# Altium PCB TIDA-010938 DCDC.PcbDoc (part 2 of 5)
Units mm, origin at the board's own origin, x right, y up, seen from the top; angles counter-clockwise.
Board outline 275 x 165 mm, 4 copper layers (Top Layer, Layer 1, Layer 2, Bottom Layer), stack 1.787 mm thick; 436 components, 216 nets, 1367 pads, 1992 vias.
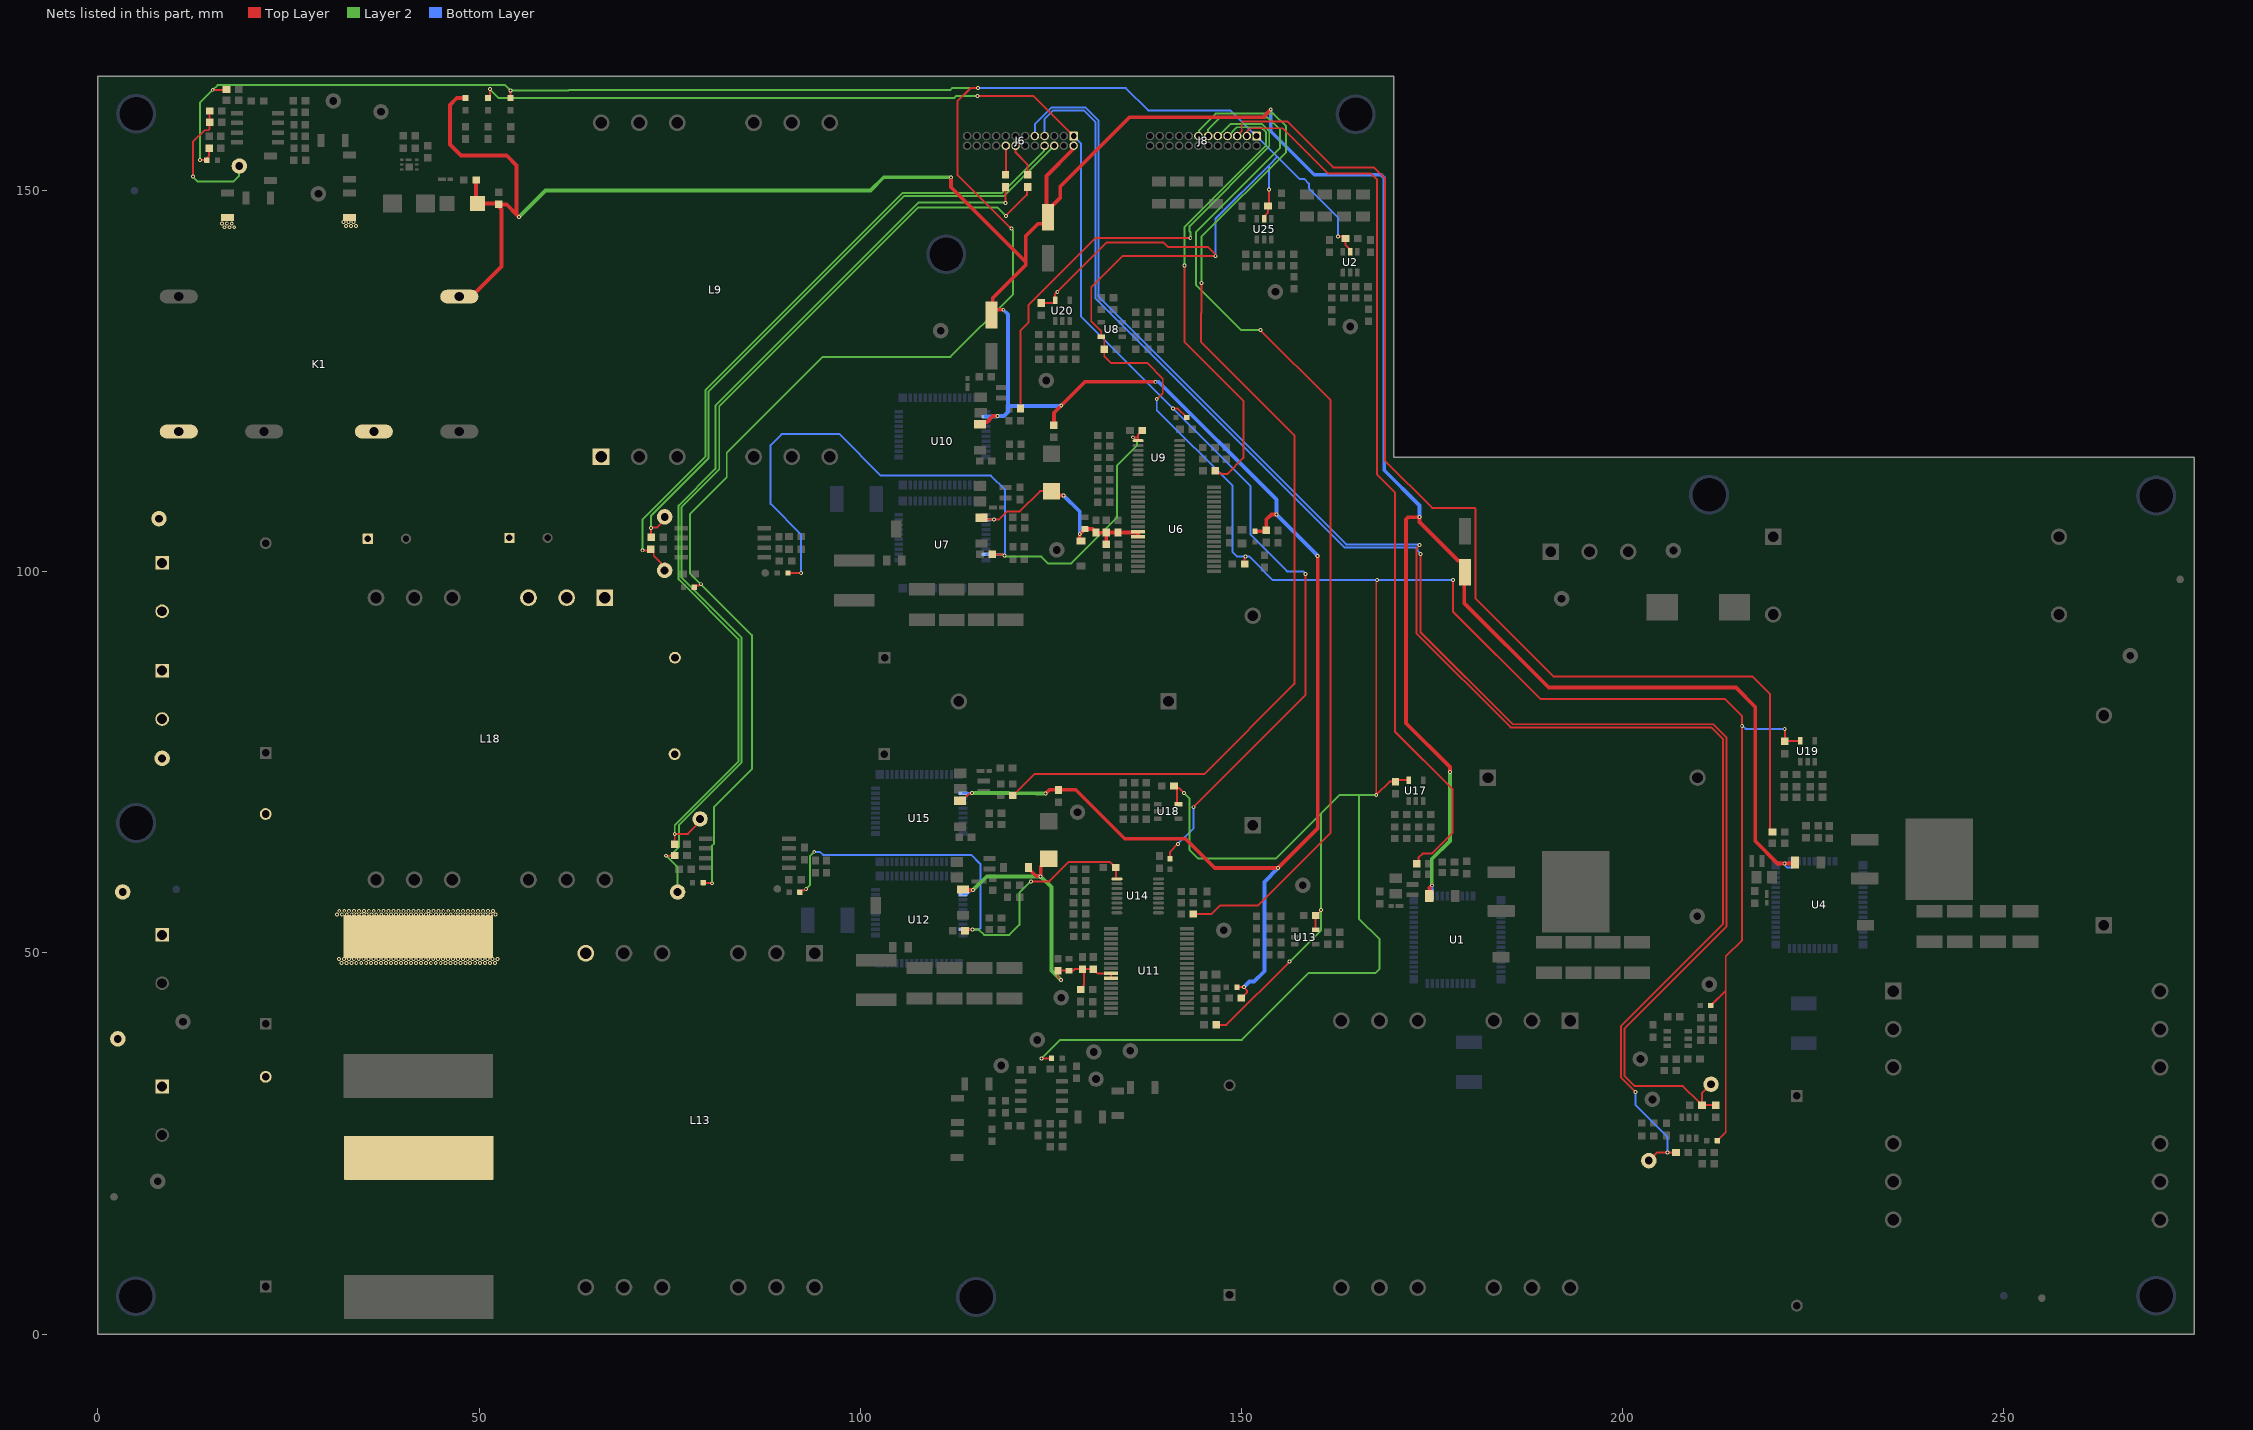
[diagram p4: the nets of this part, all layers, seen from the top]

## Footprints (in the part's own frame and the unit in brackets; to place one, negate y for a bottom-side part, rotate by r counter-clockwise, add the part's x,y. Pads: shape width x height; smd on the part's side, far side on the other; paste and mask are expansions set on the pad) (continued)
FP-B180986_PTH12-MFG [mm]
  rrect5% 2.2x2.2 hole 1.5 paste-1000 mask+0: 1(-18.5,15)
  round 2.2 hole 1.5 paste-1000 mask+0: 2(-18.5,10) 3(-18.5,5) 4(-18.5,-5) 5(-18.5,-10) 6(-18.5,-15) 7(18.5,-15) 8(18.5,-10) 9(18.5,-5) 10(18.5,5) 11(18.5,10) 12(18.5,15)
  silkscreen extent -22.12,-20.25 21.4,20.25, body extent -21.5,-20.35 21.5,20.35, height 0.25
FP-C4AKOBU4270A3YJ_RADIAL-MFG [mm]
  rrect5% 2.15x2.15 hole 1.4 paste-1000 mask+0: 1(-13.75,0)
  round 2.15 hole 1.4 paste-1000 mask+0: 2(13.75,0)
  silkscreen extent -16.35,-7.35 16.35,7.35, body extent -16.45,-7.45 16.45,7.45, height 0.25
FP-C4AKOBW5140A3JJ_RADIAL-MFG [mm]
  rrect5% 2.15x2.15 hole 1.4 paste-1000 mask+0: 1(-18.75,5.1)
  round 2.15 hole 1.4 paste-1000 mask+0: 2(18.75,5.1) 3(-18.75,-5.1) 4(18.75,-5.1)
  silkscreen extent -22.12,-14.5 21.5,14.5, body extent -21.6,-14.6 21.6,14.6, height 0.25
FP-C4AUJBU4240M1WJ_RADIAL-MFG [mm]
  rrect6% 1.55x1.55 hole 1 paste-1000 mask+0: 1(-13.75,0)
  round 1.55 hole 1 paste-1000 mask+0: 2(13.75,0)
  silkscreen extent -16.35,-5.85 16.35,5.85, body extent -16.45,-5.95 16.45,5.95, height 0.25
FP-C4AUJBU4600M18J_RADIAL-MFG [mm]
  rrect6% 1.55x1.55 hole 1 paste-1000 mask+0: 1(-13.75,0)
  round 1.55 hole 1 paste-1000 mask+0: 2(13.75,0)
  silkscreen extent -16.35,-8.35 16.35,8.35, body extent -16.45,-8.45 16.45,8.45, height 0.25
FP-C6D20065G_TO263-2-MFG [mm]
  rrect6% 1.54x3.56 smd paste+0 mask+0: 1(-2.54,-7.993) 2(2.54,-7.993)
  rrect1% 10.69x8.89 smd paste+0 mask+0: 3(0,1.773)
  silkscreen extent -5.14,-4.7 5.14,-3.05, body extent -5.45,-9.87 5.45,6.32, height 0.25
FP-CSD17318Q2_WSON6-MFG [mm]
  rrect33% 0.45x0.3 smd paste+0 mask+0: 1(-0.975,0.65) 2(-0.975,0) 3(-0.975,-0.65) 4(0.975,-0.65) 5(0.975,0) 6(0.975,0.65)
  rrect33% 0.75x0.3 smd paste-1000 mask+0: 7(0.095,-0.65)
  rrect11% 1x0.95 smd paste-1000 mask+0: 8(0,0.325)
  body extent -1.3,-1.15 1.3,1.15, height 0.25
FP-CSR0805FKR250_0805-MFG [mm]
  rrect10% 1x1.35 smd paste+0 mask+0: 1(-1,0) 2(1,0)
  silkscreen extent -0.3,-0.7 0.3,0.7, body extent -1.6,-0.8 1.6,0.8, height 0.25
FP-CSS2H-2512K-3L00F_2512-MFG [mm]
  rrect6% 1.8x3.4 smd paste+0 mask+0: 1(-2.6,0) 2(2.6,0)
  silkscreen extent -1.33,-1.63 1.33,1.63, body extent -3.17,-1.53 3.17,1.53, height 0.81
"FP-G7L-2A-X DC12_PTH_RELAY_52MM5_35MM5-MFG" [mm]
  rrect100% 5x1.8 hole 1.2 slot 4.4 at 0 deg paste-1000 mask+0: 0(18.4,9.1) 1(-18.4,9.1) 2(18.4,-8.6) 4(7.2,-8.6) 6(-7.2,-8.6) 8(-18.4,-8.6)
  silkscreen extent -26.97,-17.75 26.25,17.75, body extent -26.35,-17.85 26.35,17.85, height 0.25
FP-GB02SLT12-214_DO-214AA-MFG [mm]
  rrect5% 2.16x2.26 smd paste+0 mask+0: 1(-2.45,0) 2(2.45,0)
  silkscreen extent -4.3,-1.97 2.28,1.97, body extent -3.63,-2.07 3.63,2.07, height 0.25
"FP-KG DELLS1.22-JGKH-24_0603-MFG" [mm]
  rrect20% 1.05x0.5 smd paste-1000 mask+0: 1(-0.47,0)
  rrect20% 0.7x0.5 smd paste-1000 mask+0: 2(0.645,0)
  silkscreen extent -1.67,-0.63 0.75,0.63, body extent -1.09,-0.55 1.09,0.55, height 0.25
FP-MH1608-601Y_0603-MFG [mm]
  rrect14% 0.7x0.7 smd paste+0 mask+0: 1(-0.7,0) 2(0.7,0)
  silkscreen extent -0.87,-0.8 0.87,0.8, body extent -1.15,-0.6 1.15,0.6, height 0.25
FP-PTCEL13R102SBE_RADIAL-MFG [mm]
  rrect7% 1.35x1.35 hole 0.85 paste-1000 mask+0: 1(-2.5,0)
  round 1.35 hole 0.85 paste-1000 mask+0: 2(2.5,0)
  silkscreen extent -6.75,-3.5 6.75,3.5, body extent -6.85,-3.6 6.85,3.6, height 0.25
FP-R533R456050P0M_RADIAL-MFG [mm]
  rrect6% 1.55x1.55 hole 1 paste-1000 mask+0: 1(-13.75,0)
  round 1.55 hole 1 paste-1000 mask+0: 2(13.75,0)
  silkscreen extent -16.25,-8.15 16.25,8.15, body extent -16.35,-8.25 16.35,8.25, height 0.25
FP-SDEM20161T-4R7MS_SMD2-MFG [mm]
  rrect15% 0.65x1.6 smd paste+0 mask+0: 1(-0.675,0) 2(0.675,0)
  silkscreen extent -1.05,-1.22 1.05,1.2, body extent -1.15,-0.95 1.15,0.95, height 0.25
FP-SHF-112-01-L-D-TH_HDR24-MFG [mm]
  rrect9% 1.12x1.12 hole 0.74 paste-1000 mask+0: 1(-6.985,-0.89)
  round 1.12 hole 0.74 paste-1000 mask+0: 2(-6.985,0.38) 3(-5.715,-0.89) 4(-5.715,0.38) 5(-4.445,-0.89) 6(-4.445,0.38) 7(-3.175,-0.89) 8(-3.175,0.38) 9(-1.905,-0.89) 10(-1.905,0.38) 11(-0.635,-0.89) 12(-0.635,0.38) 13(0.635,-0.89) 14(0.635,0.38) 15(1.905,-0.89) 16(1.905,0.38) 17(3.175,-0.89) 18(3.175,0.38) 19(4.445,-0.89) 20(4.445,0.38) 21(5.715,-0.89) 22(5.715,0.38) 23(6.985,-0.89) 24(6.985,0.38)
  silkscreen extent -10.86,-3.46 10.86,2.86, body extent -10.96,-2.96 10.96,2.96, height 0.25
FP-SMBJ5350B-TP_SMB-MFG [mm]
  rrect4% 2.5x2.3 smd paste+0 mask+0: 1(-2.15,0) 2(2.15,0)
  silkscreen extent -4.12,-1.97 2.42,1.97, body extent -3.5,-2.07 3.5,2.07, height 0.25
FP-ZRB18AR61E106ME01L_0603-MFG [mm]
  rrect13% 0.75x0.9 smd paste+0 mask+0: 1(-0.775,0) 2(0.775,0)
  silkscreen extent 0,-0.5 0,0.5, body extent -1.25,-0.6 1.25,0.6, height 0.25
Harwin_S2751-46R [mm] "Test Point, SMT"
  rect 2.2x1.4 smd: 1(0,0)
  body extent -1,-0.6 1,0.6, height 1.4
IEC_HighVoltage_Small [mm]
  silkscreen extent -2.72,-2.24 2.72,2.47
IEC_HotSurface_Small [mm]
  silkscreen extent -2.72,-2.36 2.72,2.35
Keystone5001 [mil] "For Keystone 500x miniature loop terminals"
  round 80 hole 40: 1(0,0)
  silkscreen extent -52,-52 52,52, body extent -49,-49 49,49, height 182
Label_650x200 [mil] "Thermal Transfer Label"
  round 1 on Mech13: 0(0,0)
  silkscreen extent -325,-100 325,100, body extent -325,-100 325,100, height 1
Phoenix_1714955 [mm] "Terminal Block, 2x1, 6.35mm, TH"
  rect 1.8x1.8 hole 1.3: 1(-3.175,0)
  round 1.8 hole 1.3: 2(3.175,0)
  silkscreen extent -6.7,-7.9 6.35,4.6, body extent -6.92,-7.9 6.35,4.6, height 21.5
RQS0052C-C01-MFG [mm]
  rrect9% 1.15x1.1 smd paste+0 mask+0: 1(-5.725,5.2) 16(-5.725,-5.2) 27(5.725,-5.2) 42(5.725,5.2)
  rrect22% 1.15x0.45 smd paste+0 mask+0: 2(-5.725,4.225) 3(-5.725,3.575) 4(-5.725,2.925) 5(-5.725,2.275) 6(-5.725,1.625) 7(-5.725,0.975) 8(-5.725,0.325) 9(-5.725,-0.325) 10(-5.725,-0.975) 11(-5.725,-1.625) 12(-5.725,-2.275) 13(-5.725,-2.925) 14(-5.725,-3.575) 15(-5.725,-4.225) 28(5.725,-4.225) 29(5.725,-3.575) 30(5.725,-2.925) 31(5.725,-2.275) 32(5.725,-1.625) 33(5.725,-0.975) 34(5.725,-0.325) 35(5.725,0.325) 36(5.725,0.975) 37(5.725,1.625) 38(5.725,2.275) 39(5.725,2.925) 40(5.725,3.575) 41(5.725,4.225)
  rrect15% 0.665x1.15 smd paste+0 mask+0: 17(-2.043,-5.725) 52(-2.043,5.725)
  rrect22% 0.45x1.15 smd paste+0 mask+0: 18(-1.285,-5.725) 19(-0.635,-5.725) 20(0.015,-5.725) 21(0.665,-5.725) 22(1.315,-5.725) 23(1.965,-5.725) 24(2.615,-5.725) 25(3.265,-5.725) 26(3.915,-5.725) 43(3.915,5.725) 44(3.265,5.725) 45(2.615,5.725) 46(1.965,5.725) 47(1.315,5.725) 48(0.665,5.725) 49(0.015,5.725) 50(-0.635,5.725) 51(-1.285,5.725)
  silkscreen extent -7.02,-6.05 4.77,6.05, body extent -6,-6 6,6, height 1
SMA [mm] "Molded Diode, 2-Leads, Body 4.3x2.6mm, IPC Medium Density, based on OnSemi component dimensions and land pattern"
  rect 2x2 smd: 1(-2,0) 2(2,0)
  silkscreen extent -3.66,-1.57 2.79,1.58, body extent -2.6,-1.3 2.6,1.3, height 2.42
SOD-123 [mm] "On Semi recommended land pattern"
  rect 0.915x1.22 smd: 1(-1.637,0) 2(1.637,0)
  silkscreen extent -2.74,-1.17 2.03,1.17, body extent -1.93,-0.9 1.93,0.9, height 1.35
SRP1038A [mm] "SMD, 2-Leads, Body 11x10mm"
  rect 4.1x3.5 smd: 1(-4.75,0) 2(4.75,0)
  silkscreen extent -5,-5 5,5, body extent -5.2,-5 5.2,5, height 3.75
SRP2313AA [mm] "Shielded, metal alloy powder core"
  rrect2% 5.75x19.6 smd: 1(-9.125,0) 2(9.125,0)
  body extent -11.75,-11 11.75,11, height 12.61
TNPV1206 [mm] "VISHAY"
  rrect11% 0.9x1.7 smd: 1(-1.6,0) 2(1.6,0)
  silkscreen extent -2.4,-1.2 2.4,1.2, body extent -1.67,-0.87 1.67,0.87, height 0.65
TP_SM_1MM [mm] "1mm Test Point, SMT"
  round 1 smd paste-0.5: 1(0,0)
UWT_630x770 [mm] "SMD, 2-Leads, Dia 6.3mm"
  rrect6% 3.5x1.6 smd: 1(-2.7,0) 2(2.7,0)
  body extent -3.5,-3.3 3.5,3.3, height 8
WEEE_Minimum [mm] "WEEElie bin"
  silkscreen extent -2.42,-4.38 2.52,2.65
WL-SMCW_GREEN [mm] "WURTH"
  rect 0.8x0.8 smd: 1(-0.8,0) 2(0.8,0)
  silkscreen extent -1.9,-0.8 1.2,0.8, body extent -0.85,-0.45 0.85,0.45, height 0.8

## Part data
C1: library part CMP-0007470-5, "CAP, CERM, 0.1 uF, 100 V, +/- 10%, X7R, 0603", Cap_Case=0603, Manufacturer=MuRata, Supplier Part Number 1=490-6439-1-ND, TempCo=X7R, Tolerance_%=10%, Value1=Unknown, Value2=100V, ValueDisplayed=0.1uF
C2 C30 C224: library part CMP-0045188-1, "5.6 µF Film Capacitor 310V 630V Polypropylene (PP), Metallized Radial", Digikey Part Number=399-R533R456050P0M-ND, Manufacturer=KEMET, Mouser Part Number=80-R533R456050P0M, Operating Temperature Range="-40°C to +110°C", Tolerance_%=20%, ValueDisplayed=5.6uF, Voltage Ac Rating X=310V
C3 C4 C10 C24: library part CMP-0045062-1, "2.7 µF Film Capacitor 900V Polypropylene (PP), Metallized Radial", Digikey Part Number=399-C4AKOBU4270A3YJ-ND, Manufacturer=Kemet, Mouser Part Number=80-C4AKOBU4270A3YJ, Operating Temperature Range="-55°C to +135°C", Tolerance_%=5%, ValueDisplayed=2.7uF
C5 C115 C144: library part CMP-0081462-1, "CAP, AL, 100 µF, 25 V, +/- 20%, SMD", Cap_Case=6.3x7.7mm, Manufacturer=Nichicon, Supplier Part Number 1=493-2190-1-ND, Tolerance_%=20%, Value2=25V, ValueDisplayed=100µF
C6 C20 C34 C59 C68 C93: library part CMP-0750154-1, "CAP, CERM, 10 µF, 25 V,+/- 10%, X7R, AEC-Q200 Grade 1, 1206", Cap_Case=1206, Manufacturer="Taiyo Yuden", TempCo=X7R, Tolerance_%=10%, Value2=25V, ValueDisplayed=10µF
C7 C11 C12 C14 C15 C16 C19 C22 C25 C26 C28 C29 C35 C45 C54 C55 C58 C62 C64 C67 C69 C78 C79 C82 C83 C86 C87 C88 C89 C90 C91 C92 C96 C97 C98 C112 C116 C118 C120 C122 C142 C151 C152 C153: library part CMP-0007442-5, "CAP, CERM, 220 pF, 50 V, +/- 10%, X7R, 0603", Cap_Case=0603, Manufacturer=MuRata, Supplier Part Number 1=490-1483-1-ND, TempCo=X7R, Tolerance_%=10%, Value1=Unknown, Value2=50V, ValueDisplayed=220pF
C8 C21 C31 C36 C37 C48 C49 C52 C56 C57 C61 C70 C71 C95 C108 C124 C125 C128 C129 C146: library part CMP-0006752-5, "CAP, CERM, 0.1 uF, 25 V, +/- 5%, X7R, 0603", Cap_Case=0603, Manufacturer=AVX, Supplier Part Number 1=478-3713-1-ND, TempCo=X7R, Tolerance_%=5%, Value1="0.05 ohm", Value2=25V, ValueDisplayed=0.1uF
C9 C23: library part CMP-0045101-1, "6 µF Film Capacitor 700V Polypropylene (PP), Metallized Radial", Digikey Part Number=399-C4AUJBU4600M18J-ND, Manufacturer=KEMET, Mouser Part Number=80-C4AUJBU4600M18J, Operating Temperature Range="-55°C to +105°C", Tolerance_%=5%, ValueDisplayed=6uF
C13 C27 C46 C65 C80 C99: library part CMP-0007975-2, "CAP, CERM, 2.2 uF, 25 V, +/- 10%, X7R, AEC-Q200 Grade 1, 0805", Cap_Case=0805, Manufacturer=TDK, Supplier Part Number 1=445-6965-1-ND, TempCo=X7R, Tolerance_%=10%, Value1=Unknown, Value2=25V, ValueDisplayed=2.2uF
C17 C32 C38 C72: library part CMP-0086152-1, "CAP, CERM, 1 µF, 25 V,+/- 10%, X5R, 0603", Cap_Case=0603, Manufacturer="Taiyo Yuden", TempCo=X5R, Tolerance_%=10%, Value2=25V, ValueDisplayed=1µF
C18 C33 C154: library part CMP-0079721-1, "CAP, CERM, 0.01 µF, 25 V,+/- 10%, X7R, 0603", Cap_Case=0603, Manufacturer="Presidio Components", TempCo=X7R, Tolerance_%=10%, Value2=25V, ValueDisplayed=0.01µF
C39 C73: library part CMP-0009474-2, "CAP, CERM, 20 uF, 16 V, +/- 20%, X5R, 0704", Cap_Case=0704, Manufacturer=MuRata, TempCo=X5R, Tolerance_%=20%, Value1=Unknown, Value2=16V, ValueDisplayed=20uF
C40 C74: library part CMP-0007507-5, "CAP, CERM, 10 uF, 25 V, +/- 20%, X5R, 0603", Cap_Case=0603, Manufacturer="Taiyo Yuden", TempCo=X5R, Tolerance_%=20%, Value1=Unknown, Value2=25V, ValueDisplayed=10uF
C41 C75: library part CMP-0094458-1, "10µF ±20% 25V Ceramic Capacitor X5R 0603 (1608 Metric)", Digikey Part Number=490-10991-1-ND, Manufacturer="Murata Electronics", Mouser Part Number=81-ZRB18AR61E106ME1L, Operating Temperature Range="-55°C to +85°C", Temperature Characteristic=X5R, Tolerance_%=20%, ValueDisplayed=10uF
C42 C76: library part CMP-0007209-4, "CAP, CERM, 330 pF, 50 V, +/- 5%, C0G/NP0, 0603", Cap_Case=0603, Manufacturer=MuRata, Supplier Part Number 1=490-1439-1-ND, TempCo=C0G/NP0, Tolerance_%=5%, Value1=Unknown, Value2=50V, ValueDisplayed=330pF
C43 C50 C51 C77 C84 C85 C117 C119: library part CMP-0006837-4, "CAP, CERM, 0.1 uF, 50 V, +/- 10%, X7R, 0603", Cap_Case=0603, Manufacturer="Wurth Elektronik", TempCo=X7R, Tolerance_%=10%, Value1=Unknown, Value2=50V, ValueDisplayed=0.1uF
C44 C53: library part CMP-0007082-4, "CAP, CERM, 0.01 uF, 100 V, +/- 10%, X7R, AEC-Q200 Grade 1, 0603", Cap_Case=0603, Manufacturer=TDK, Supplier Part Number 1=445-5812-1-ND, TempCo=X7R, Tolerance_%=10%, Value1="0.235428 ohm", Value2=100V, ValueDisplayed=0.01uF
C47 C81: library part CMP-0750039-1, "CAP, CERM, 0.01 µF, 50 V,+/- 10%, X7R, 0603", Cap_Case=0603, Manufacturer="Wurth Elektronik", TempCo=X7R, Tolerance_%=10%, Value2=50V, ValueDisplayed=0.01µF
C60 C94: library part CMP-0045063-1, "2.4 µF Film Capacitor 700V Polypropylene (PP), Metallized Radial", Digikey Part Number=399-C4AUJBU4240M1WJ-ND, Manufacturer=KEMET, Mouser Part Number=80-C4AUJBU4240M1WJ, Operating Temperature Range="-55°C to +105°C", Tolerance_%=5%, ValueDisplayed=2.4uF
C63 C66: library part CMP-0086177-1, "CAP, CERM, 0.47 µF, 1000 V,+/- 10%, X7R, AEC-Q200 Grade 1, 2220", Cap_Case=2220, Manufacturer="Knowles Capacitors", TempCo=X7R, Tolerance_%=10%, Value2=1000V, ValueDisplayed=0.47µF
C100 C101 C106 C107 C110 C111 C113 C126 C127 C130 C131 C133 C134 C135 C140 C141: library part CMP-0009326-2, "0.03 µF ±10% 1000V (1kV) Ceramic Capacitor C0G, NP0 1812 (4532 Metric)", Cap_Case=1812, Manufacturer=Kemet, Supplier Part Number 1=399-C1812C303KDGLCAUTOTR-ND, TempCo=NP0, Tolerance_%=10%, Value1=Unknown, Value2=1000V, ValueDisplayed=0.03uF
C102 C132 C155: library part CMP-0006979-5, "CAP, CERM, 0.1 uF, 25 V, +/- 10%, X7R, 0603", Cap_Case=0603, Manufacturer=Kemet, Supplier Part Number 1=399-5345-1-ND, TempCo=X7R, Tolerance_%=10%, Value1=Unknown, Value2=25V, ValueDisplayed=0.1uF
C103 C104 C105 C109: library part CMP-0007189-4, "CAP, CERM, 1600 pF, 50 V, +/- 5%, C0G/NP0, 0603", Cap_Case=0603, Manufacturer=MuRata, Supplier Part Number 1=490-1456-1-ND, TempCo=C0G/NP0, Tolerance_%=5%, Value1=Unknown, Value2=50V, ValueDisplayed=1600pF
C143: library part CMP-0045770-1, "14 µF Film Capacitor 900V Polypropylene (PP), Metallized Radial - 4 Leads", Digikey Part Number=399-C4AKOBW5140A3JJ-ND, Manufacturer=Kemet, Mouser Part Number=80-C4AKOBW5140A3JJ, Operating Temperature Range="-55°C to +135°C", Tolerance_%=5%, ValueDisplayed=14uF
D1 D3: library part CMP-0042032-1, "Schottky Diode 650 V 20A Surface Mount TO-263-2", Digikey Part Number=1697-C6D20065G-ND, Forward Current=64A, Manufacturer=Wolfspeed, Max Surge Forward Current=135A, Mouser Part Number=941-C6D20065G, Operating Temperature Range="-55°C to +175°C", Peak Reverse Current=5uA, ValueDisplayed=1153pF
D5 D8: library part CMP-0095009-1, "Diode Silicon Carbide Schottky 1200 V 2A (DC) Surface Mount DO-214AA", Digikey Part Number=1242-1170-1-ND, Forward Current=2A, Manufacturer="GeneSiC Semiconductor", Max Surge Forward Current=20A, Mouser Part Number=905-GB02SLT12-214, Operating Temperature Range="-55°C to +175°C", Peak Reverse Current=1uA, ValueDisplayed=122pF
D6 D9: library part CMP-0005769-4, "Diode, Zener, 16 V, 500 mW, AEC-Q101, SOD-123", Manufacturer="Diodes Inc.", Power_W=500mW, Value1=0.5W
D11: library part CMP-0097215-1, "Zener Diode 13 V 5 W ±5% Surface Mount DO-214AA (SMB)", Digikey Part Number=SMBJ5350B-TPMSCT-ND, Manufacturer=MCC, Max Reverse Leakage Current=1uA, Mouser Part Number=833-SMBJ5350B-TP, Operating Temperature Range="-55°C to +150°C", Power_W=5W
D12: library part CMP-0029023-2, "Diode, Superfast Rectifier, 150 V, 1 A, SMA", Manufacturer="Diodes Inc.", Value1=1A, Value2=0.92V
D13 D15 D16: library part CMP-0002894-2, "LED, Green, SMD", Color=green, Manufacturer="Wurth Elektronik", Value1=W, Value2=2V
D14 D17 D18 D19 D20 D21 D22: library part CMP-0093310-1, "Standard LEDs - SMD Green TOPLED E 1608", Color=Green, Forward Current=2mA, Manufacturer="Osram Opto", Mouser Part Number=720-KGDELLS122A4849, Operating Temperature Range="-40°C to +110°C"
FB1 FB2 FB3 FB4 FB5 FB6 FB9 FB10 FB11 FB12 FB13 FB14: library part CMP-0037505-1, "600 Ohms @ 100 MHz 1 Power, Signal Line Ferrite Bead 0603 (1608 Metric) 1A 200mOhm", Digikey Part Number=MH1608-601YCT-ND, Impedance At Frequency="600Ω @ 100MHz", Manufacturer=Bourns, Mouser Part Number=652-MH1608-601Y, Operating Temperature Range="-55°C to +125°C", Test Frequency=100MHz, Tolerance_%=25%
FID1 FID2 FID3 FID4 FID5 FID6: library part CMP-0077181-1, "Fiducial mark.  There is nothing to buy or mount.", Manufacturer=N/A
J1: library part CMP-0094328-1, "3 Position Terminal Block Header, Male Pins, Shrouded (4 Side) 0.200\" (5.08mm) Vertical - Through Hole", Current_A=15A, Digikey Part Number=A98423-ND, Manufacturer="TE Connectivity", Mouser Part Number=571-796636-3, Operating Temperature Range="-40°C to +105°C", Voltage_V=300V
J2 J3 J4 J5: library part CMP-0055505-1, "Terminal Block, 2x1, 6.35mm, Green, TH", Color=Green, Manufacturer="Phoenix Contact", Supplier Part Number 1=277-1269-ND
J6 J8: library part CMP-0003796-1, "Conn Shrouded Header (4 Sides) HDR 24 POS 1.27mm Solder ST Top Entry Thru-Hole Tube", Digikey Part Number=SHF-112-01-L-D-TH-ND, Manufacturer=Samtec, Mouser Part Number=200-SHF11201LDTH, Operating Temperature Range="-55°C to +125°C"
K1: library part CMP-0093885-1, "General Purpose Relay DPST-NO (2 Form A) 12VDC Coil Through Hole", Coil Current_A=191.7mA, Coil Power_W=2.3W, Coil Resistance=63Ω, Coil Voltage_VDC=12V, Contact Rating_A=30A, Digikey Part Number=Z6085-ND, Manufacturer=Omron, Mouser Part Number=653-G7L2AXDC12, Operating Temperature Range="-40°C to +85°C"
L1 L4: library part CMP-0049239-1, "Double Boost Inductor", Manufacturer=Bourns, Operating Temperature Range="-40°C to +125°C", Test Frequency=100kHz, Tolerance_%=10%
L2 L5 L7 L10 L11 L14: library part CMP-0089347-1, "4.7µH Unshielded Inductor 1.1A 426mOhm Max 0806 (2016 Metric)", Digikey Part Number=2037-SDEM20161T-4R7MSCT-ND, Manufacturer=Cyntec, Operating Temperature Range="-55°C to +125°C", Test Frequency=1MHz, Tolerance_%=20%
L3: library part CMP-0056795-1, "Inductor, Shielded, Powdered Iron, 1 uH, 18 A, 0.003 ohm, AEC-Q200 Grade 1, SMD", Manufacturer=Bourns, Supplier Part Number 1=SRP1038A-1R0MCT-ND, Value1="0.003 ohm", Value2=18A, ValueDisplayed=1uH
L6 L8: library part CMP-0081037-1, "Inductor, Shielded, Metal Composite, 22 µH, 14 A, 0.011 ohm, AEC-Q200 Grade 0, SMD", Manufacturer=Bourns, Supplier Part Number 1=SRP2313AA-220MCT-ND, Value1="0.011 ohm", Value2=14A, ValueDisplayed=22µH
L9 L13: library part CMP-0048784-1, "Bi-directional DC-DC Inductor 186.7µH ± 10%", Manufacturer=Bourns, Operating Temperature Range="-40°C to +85°C", Test Frequency=100kHz, Tolerance_%=10%
L18: library part CMP-0047896-1, "Inductor 22μH 4.7mΩ", Manufacturer=Bourns, Operating Temperature Range=to, Test Frequency=100kHz
LBL1: library part CMP-0003625-1, "Thermal Transfer Printable Labels, 0.650\" W x 0.200\" H - 10,000 per roll", Manufacturer=Brady, Supplier Part Number 1=97C5133
LOGO1: library part CMP-0074837-1, "IEC 61010-1 Hot Surface Warning"
Logo2: library part CMP-0074844-1
Logo3: library part CMP-0074847-1, "FCC_disclaimer"
Logo4: library part CMP-0074769-1
LOGO5: library part CMP-0074835-1, "IEC 61010-1 High Voltage Warning"
MP1 MP2 MP3 MP4 MP5 MP6 MP7 MP8 MP9: library part CMP-0040203-1, "Round Spacer Unthreaded Steel 0.059\" (1.50mm)", Digikey Part Number=732-7071-1-ND, Manufacturer="Wurth Electronics", Mouser Part Number=710-9774015960R, Operating Temperature Range="-55°C to +150°C"
Q1: library part CMP-0076725-1, "30-V N-Channel NexFET™ Power MOSFET", Manufacturer="Texas Instruments"
R1 R3 R4 R5 R8 R11 R13 R14 R15 R19 R24 R26 R34 R35 R37 R38 R40 R49 R51 R59 R60 R62 R63 R65 R72 R75 R76 R77 R78 R83 R84 R85 R86 R87 R89 R144 R146 R149 R150 R151 R152 R155 R158 R159: library part CMP-0023572-3, "RES, 56, 0.1%, 0.1 W, 0603", Manufacturer="Susumu Co Ltd", Power_W=100mW, Supplier Part Number 1=RG16P56.0BCT-ND, TempCo="25 ppm/C", Tolerance_%=0.1%, Value2=0.1W, Value_Code=56R0, ValueDisplayed=56
R2 R88: library part CMP-0043438-1, "PTCEL Series 850 V 1 kOhm ±30 % Radial Inrush Current Limiter PTC Thermistor", Digikey Part Number=56-PTCEL13R102SBE-ND, Hold Current=30mA, Manufacturer=Vishay, Max Current=40A, Mouser Part Number=594-PTCEL13R102SBE, Operating Temperature Range="-40°C to +105°C", Tolerance_%=30%
R6 R16 R32 R45 R57 R70: library part CMP-0022906-5, "RES, 20.0 k, 1%, 0.1 W, 0603", Manufacturer=Yageo, Power_W=100mW, Supplier Part Number 1=311-20.0KHRCT-ND, TempCo="100 ppm/C", Tolerance_%=1%, Value2=0.1W, Value_Code=20k0, ValueDisplayed=20.0k
R7 R147: library part CMP-0024836-3, "RES, 1.67 k, 0.5%, 0.1 W, 0603", Manufacturer="Yageo America", Power_W=100mW, TempCo="50 ppm/C", Tolerance_%=0.5%, Value2=0.1W, Value_Code=1k67, ValueDisplayed=1.67k
R9 R10 R20 R56 R58 R67 R71 R96: library part CMP-0023661-3, "RES, 10.0, 0.1%, 0.1 W, 0603", Manufacturer="Yageo America", Power_W=100mW, TempCo="25 ppm/C", Tolerance_%=0.1%, Value2=0.1W, Value_Code=10R0, ValueDisplayed=10.0
R12 R39 R41 R64 R79 R80 R81 R82 R90 R91 R92 R93 R106 R125 R127 R129 R131 R139 R140 R141 R156 R157: library part CMP-0023404-3, "RES, 10.0 k, 0.1%, 0.1 W, 0603", Manufacturer="Susumu Co Ltd", Power_W=100mW, Supplier Part Number 1=RG16P10.0KBCT-ND, TempCo="25 ppm/C", Tolerance_%=0.1%, Value2=0.1W, Value_Code=10k0, ValueDisplayed=10.0k
R17 R18: library part CMP-0043791-1, "Res Metal Strip 2512 0.003 Ohm 1% 4W ±75ppm/C Pad SMD Automotive T/R", Digikey Part Number=CSS2H-2512K-3L00FCT-ND, Manufacturer=Bourns, Mouser Part Number=652-CSS2H2512K3L00F, Operating Temperature Range="-55°C to +170°C", Power_W=4W, TempCo=75ppm/°C, Tolerance_%=1%
R21 R46: library part CMP-0025114-2, "RES, 2.00, 0.5%, 0.1 W, 0603", Manufacturer="Yageo America", Power_W=100mW, TempCo="50 ppm/C", Tolerance_%=0.5%, Value2=0.1W, Value_Code=2R00, ValueDisplayed=2.00
R22 R25 R47 R50: library part CMP-0022685-3, "RES, 12.0 k, 1%, 0.1 W, 0603", Manufacturer=Panasonic, Power_W=100mW, Supplier Part Number 1=P12.0KHCT-ND, TempCo="100 ppm/C", Tolerance_%=1%, Value2=0.1W, Value_Code=12k0, ValueDisplayed=12.0k
R23 R48: library part CMP-0025200-2, "RES, 38.8 k, 0.5%, 0.1 W, 0603", Manufacturer="Yageo America", Power_W=100mW, TempCo="50 ppm/C", Tolerance_%=0.5%, Value2=0.1W, Value_Code=38k8, ValueDisplayed=38.8k
R27 R52: library part CMP-0024286-2, "RES, 4.02 k, 0.1%, 0.1 W, 0603", Manufacturer="Yageo America", Power_W=100mW, TempCo="25 ppm/C", Tolerance_%=0.1%, Value2=0.1W, Value_Code=4k02, ValueDisplayed=4.02k
R28 R30 R31 R33 R36 R42 R43 R44 R53 R68 R69 R74: library part CMP-0018816-2, "RES, 680 k, 0.1%, 1 W, 1206", Manufacturer="Vishay Draloric", Power_W=1W, Supplier Part Number 1=541-2317-1-ND, TempCo="25 ppm/C", Tolerance_%=0.1%, Value_Code=680k
R29 R54 R145: library part CMP-0023404-1, "RES, 10.0 k, 0.1%, 0.1 W, 0603", Manufacturer="Susumu Co Ltd", Power_W=100mW, Supplier Part Number 1=RG16P10.0KBCT-ND, TempCo="25 ppm/C", Tolerance_%=0.1%, Value2=0.1W, Value_Code=10k0, ValueDisplayed=10.0k
R55 R97: library part CMP-0081973-1, "RES, 0, 0%, 0.25 W, AEC-Q200 Grade 0, 0603", Manufacturer=Vishay-Dale, Power_W=250mW, Supplier Part Number 1=541-2779-1-ND, Tolerance_%=0%, Value2=0.25W, Value_Code=0
R61 R66 R73 R95: library part CMP-0023188-5, "RES, 56.0, 1%, 0.1 W, 0603", Manufacturer=Yageo, Power_W=100mW, Supplier Part Number 1=311-56.0HRCT-ND, TempCo="100 ppm/C", Tolerance_%=1%, Value2=0.1W, Value_Code=56R0, ValueDisplayed=56.0
R94 R98: library part CMP-0088568-2, "250 mOhms ±1% 0.25W, 1/4W Chip Resistor 0805 (2012 Metric) Current Sense Thick Film", Digikey Part Number=CSR0805FKR250CT-ND, Manufacturer="Stackpole Electronics Inc", Operating Temperature Range="-55°C to +155°C", Power_W=250mW, TempCo=200ppm/°C, Tolerance_%=1%
R105 R132 R133 R135 R136 R138: library part CMP-0025933-5, "RES, 5.6 k, 5%, 0.1 W, 0603", Manufacturer=Yageo, Power_W=100mW, Supplier Part Number 1=311-5.6KGRCT-ND, TempCo="100 ppm/C", Tolerance_%=5%, Value2=0.1W, Value_Code=5k60, ValueDisplayed=5.6k
R107 R111: library part CMP-0022751-4, "RES, 10.0, 1%, 0.1 W, 0603", Manufacturer=Yageo, Power_W=100mW, Supplier Part Number 1=311-10.0HRCT-ND, TempCo="100 ppm/C", Tolerance_%=1%, Value2=0.1W, Value_Code=10R0, ValueDisplayed=10.0
R108 R109 R112 R113 R116 R117 R121: library part CMP-0023286-5, "RES, 80.6, 1%, 0.1 W, 0603", Manufacturer=Yageo, Power_W=100mW, Supplier Part Number 1=311-80.6HRCT-ND, TempCo="100 ppm/C", Tolerance_%=1%, Value2=0.1W, Value_Code=80R6, ValueDisplayed=80.6
R120: library part CMP-0023286-5, "RES, 80.6, 1%, 0.1 W, 0603", Manufacturer=Yageo, Power_W=100mW, Supplier Part Number 1=311-80.6HRCT-ND, TempCo="100 ppm/C", Tolerance_%=1%, Value2=0.1W, Value_Code=80R6
R134 R137: library part CMP-0084746-1, "RES, 0.001, 1%, 5 W, AEC-Q200 Grade 0, 6.35x3.05mm", Manufacturer=Bourns, Power_W=5W, TempCo="75 ppm/C", Tolerance_%=1%, Value_Code=1L000, ValueDisplayed=0.001
R148 R160 R161 R162 R163 R164 R165 R166: library part CMP-0018170-2, "RES, 2.20, 1%, 0.25 W, 1206", Manufacturer="Yageo America", Power_W=250mW, Supplier Part Number 1=311-2.20FRCT-ND, TempCo="200 ppm/C", Tolerance_%=1%, Value2=0.25W, Value_Code=2R20, ValueDisplayed=2.20
R153: library part CMP-0082532-1, "RES, 499, 1%, 0.1 W, 0603", Manufacturer=Vishay-Dale, Power_W=100mW, Supplier Part Number 1=541-3986-1-ND, TempCo="100 ppm/C", Tolerance_%=1%, Value2=0.1W, Value_Code=499R, ValueDisplayed=499
R154: library part CMP-0024934-2, "RES, 218, 0.5%, 0.1 W, 0603", Manufacturer="Yageo America", Power_W=100mW, TempCo="50 ppm/C", Tolerance_%=0.5%, Value2=0.1W, Value_Code=218R, ValueDisplayed=218
TP1 TP2 TP3 TP4 TP5 TP6 TP13 TP14 TP15 TP17 TP18 TP19 TP20 TP21 TP22 TP23 TP24 TP27 TP28 TP29 TP30 TP31 TP32 TP33 TP34 TP35 TP36 TP37 TP38 TP39 TP40 TP41 TP42 TP43 TP44 TP45 TP46: library part CMP-0055138-2, "Test Point, Miniature, Black, TH", Color=Black, Manufacturer="Keystone Electronics", Supplier Part Number 1=36-5001-ND
TP7 TP8: library part CMP-0003825-1, "1mm Test Point, SMT", Manufacturer=Any
TP9 TP10 TP12 TP16: library part CMP-0003968-1, "Test Point, SMT", Manufacturer=Harwin, Supplier Part Number 1=952-2664-1-ND
U1 U4 U7 U10 U12 U15: library part CMP-0094891-1, "650-V 30-mΩ GaN FET with Integrated Driver, Protection, and Temperature Reporting", Manufacturer="Texas Instruments", Max Supply Voltage=18V, Min Supply Voltage=7.5V, Nominal Supply Current=16mA, Operating Temperature Range="-40°C to +150°C", Output Voltage=520V
U2 U25: library part CMP-0051910-1, "Dual Buffer Gate, DBV0006A, LARGE T&R", F @ Nom Voltage(Max)(Mhz)=150, Generic Part Number=SN74LVC2G34, ICC @ Nom Voltage(Max)(mA)=0.01, Manufacturer="Texas Instruments", Operating Temperature Range(C)="-40 to 125,-40 to 85", Rating=Catalog, tpd @ Nom Voltage(Max)(ns)=8.6,4.4,4.1,3.2, Voltage(Nom)(V)=1.8,2.5,3.3,5
U3 U5: library part CMP-0013232-2, "Bidirectional, Low- and High-Side Measurement, Multichannel, Voltage Output, Current-Sense Amplifier, DBV0006A (SOT-6)", Alternate Manufacturer="Texas Instruments"
U6 U11: library part CMP-0033793-2, "Automotive 1.5-W, 12-V VIN / 12-VOUT, 15-V VIN / 15-V VOUT, HighDensity, > 5-kVRMS, Isolated DC/DC Module", Manufacturer="Texas Instruments", Max Supply Voltage=18V, Min Supply Voltage=9V, Nominal Supply Current=200-270mA, Operating Temperature Range="-40°C to +150°C", Output Voltage=10-18V, Switching Frequency=18MHz
U8 U13 U17 U18 U19 U20: library part CMP-0051571-2, "Single 2-Input Positive-AND Gate, DBV0005A, SMALL T&R", Alternate Manufacturer="Texas Instruments", F @ Nom Voltage(Max)(Mhz)=150, Generic Part Number=SN74LVC1G08, ICC @ Nom Voltage(Max)(mA)=0.01, Operating Temperature Range(C)="-40 to 125,-40 to 85", Rating=Catalog, tpd @ Nom Voltage(Max)(ns)=4.5,6,4,5, Voltage(Nom)(V)=1.8,2.5,3.3,5
U9 U14: library part CMP-0013040-3, "High Speed, Robust EMC Quad-Channel Digital Isolators, DBQ0016A (SSOP-16)", Alternate Manufacturer="Texas Instruments", Alternate PartNumber=ISO7741DBQ
U16 U23: library part CMP-0097119-1, "Precision, Zero-Drift, Zero-Crossover, True Rail-to-Rail, Input/Output Operational Amplifiers", Digikey Part Number=296-OPA2388IDRCT-ND, Input Bias Current=0.00003uA, Input Offset Voltage=0.00025mV, Manufacturer="Texas Instruments", Max Dual Supply Voltage=2.75V, Max Supply Voltage=5.5V, Min Dual Supply Voltage=1.25V, Min Supply Voltage=2.5V, Mouser Part Number=595-OPA2388IDR, Nominal Supply Current=1.7-1.9mA, Operating Temperature Range="-40°C to +125°C", Output Current Per Channel=30-60mA, Voltage Gain=126-148dB
U21 U22: library part CMP-0080671-1, "Precision Reinforced Isolated Amplifier for Current Sensing, DWV0008A (SOIC-8)", Alternate Manufacturer="Texas Instruments", Alternate PartNumber=AMC1302DWVR
ZZ1: library part CMP-0003616-3
ZZ2: library part CMP-0077236-1
ZZ3: library part CMP-0077237-1
ZZ4: library part CMP-0077238-1

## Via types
v1: diameter 0.508, hole 0.254, Top Layer to Bottom Layer, tented both sides, 1977 vias
v2: diameter 0.508, hole 0.254, Top Layer to Bottom Layer, 15 vias

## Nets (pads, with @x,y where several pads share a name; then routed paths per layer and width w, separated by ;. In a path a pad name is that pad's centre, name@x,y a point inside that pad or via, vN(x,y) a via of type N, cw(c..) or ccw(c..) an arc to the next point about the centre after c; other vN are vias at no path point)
1V65_HVN: C154.1 R26.2 TP33.1 | length 17.7
  Top Layer w0.254: v1(12.456,151.842) 12.456,156.382 13.997,157.922 14.456,157.922 14.661,158.127 C154.1@14.661,160.447
  Layer 2 w0.254: v1(12.456,151.842) 13.102,151.196 17.736,151.196 18.524,151.983 18.524,153.202 TP33.1@18.552,153.231
3V3_HVN: C52.1 C117.1 C119.1 C124.1 C125.1 C128.1 C129.1 C132.2 C146.1 D16.2 FB1.1 FB2.1 FB3.1 FB11.1 FB12.1 FB13.1 J8.1 R12.1 R22.1 R47.1 U2.5 U8.5 U13.5 U17.5 U18.5 U19.5 U20.5 U25.5 | length 769
  Top Layer w0.254: v1(13.364,154.004) FB11.1@14.286,154.004 ; FB11.1@14.286,154.25 14.586,154.55 C132.2@14.586,155.545 ; v1@15.013,163.275 v1(15.062,163.226) 16.834,163.226 R12.1@16.858,163.25 ; D16.2@54.142,162.336 v1(54.142,163.123) ; FB12.1@78.219,97.971 78.442,98.194 78.842,98.194 79.02,98.372 v1(79.089,98.372) ; FB13.1@79.393,59.23 79.434,59.189 80.495,59.189 v1(80.536,59.149) ; v1(115.427,163.453) 114.46,163.453 112.732,161.725 112.732,152.113 v1(119.822,145.023) ; C129.1@123.725,135.253 125.366,135.253 125.558,135.445 U20.5@125.558,135.645 125.558,136.462 125.824,136.728 v1(125.845,136.728) 132.317,143.2 139.77,143.2 140.338,142.632 145.6,142.632 146.549,141.683 146.549,141.449 v1(146.598,141.4) 134.364,141.4 130.3,137.336 130.3,132.887 131.614,131.573 U8.5@131.614,130.835 131.814,130.835 132.006,130.643 C52.1@132.006,129.198 132.006,128.269 132.875,127.4 137.623,127.4 139.677,125.346 139.677,123.428 v1(138.895,122.646) ; v1(123.786,36.175) FB3.1@125.075,36.175 ; C125.1@141.152,71.905 141.177,71.905 C125.1@141.418,71.664 ; U18.5@141.751,69.513 141.724,69.513 141.551,69.686 141.551,71.408 141.525,71.434 141.525,71.557 C125.1@141.418,71.664 ; v1(142.449,70.994) 141.779,71.664 C125.1@141.418,71.664 ; R47.1@146.687,40.569 148.023,40.569 v1@156.318,48.865 ; R22.1@150.416,101.013 150.416,101.835 150.529,101.948 v1(150.529,102.017) v1@150.48,102.065 ; U25.5@152.98,146.336 153.153,146.509 153.153,146.789 153.477,147.113 C119.1@153.477,147.969 153.621,148.113 v1(153.621,150.158) ; U13.5@159.73,53.028 159.73,54.888 C146.1@159.768,54.926 v1@160.472,55.63 ; v1(162.655,143.991) 163.384,143.991 C117.1@163.653,143.722 163.653,142.866 164.078,142.441 164.078,142.181 U2.5@164.251,142.008 ; v1(167.808,98.903) 167.808,98.834 167.688,98.714 v1(167.688,70.738) 169.431,72.481 C124.1@170.221,72.481 170.418,72.678 U17.5@171.935,72.678 ; v1(177.752,98.903) 177.752,94.79 189.245,83.298 213.434,83.298 215.691,81.042 v1(215.691,79.754) 215.691,51.697 213.531,49.537 213.531,45.059 ; FB2.1@211.536,43.064 FB2.1@211.58,43.108 213.531,45.059 ; FB1.1@212.432,25.384 213.531,26.483 213.531,45.059 ; v1(221.263,79.388) 221.282,79.369 C128.1@221.282,77.748 221.357,77.823 U19.5@223.312,77.823
  Layer 2 w0.254: v1@13.364,154.25 13.364,161.528 v1(15.062,163.226) 15.69,163.854 53.41,163.854 v1(54.142,163.123) 61.704,163.123 61.78,163.199 111.772,163.199 112.026,163.453 v1(115.427,163.453) ; v1(80.536,59.149) 80.536,64.041 80.835,64.341 80.835,69.165 85.77,74.099 85.77,91.691 v1(79.089,98.372) 77.636,99.825 77.636,107.524 82.485,112.373 82.485,115.612 95.052,128.18 111.817,128.18 120.051,136.414 120.051,144.747 119.822,144.976 v1(119.822,145.023) ; v1(123.786,36.175) 126.222,38.611 150.048,38.611 158.788,47.35 167.571,47.35 168.131,47.911 168.131,51.794 165.411,54.515 165.411,70.738 ; v1(142.449,70.994) 143.164,70.279 143.164,63.517 144.281,62.4 154.545,62.4 160.459,68.314 ; v1@156.318,48.865 160.459,53.005 v1(160.459,55.623) 160.459,68.314 ; v1(167.688,70.738) 165.411,70.738 ; 160.459,68.314 162.884,70.738 165.411,70.738
  Bottom Layer w0.254: v1(115.427,163.453) 134.839,163.453 137.772,160.52 148.545,160.52 151.466,157.599 151.552,157.599 154.719,154.432 ; v1(138.895,122.646) 138.895,121.212 148.844,111.263 148.844,102.574 149.4,102.017 v1(150.529,102.017) 151.013,102.017 154.126,98.903 v1(167.808,98.903) v1(177.752,98.903) ; v1(146.598,141.4) 146.598,146.312 153.621,153.334 ; v1(153.621,150.158) 153.621,153.334 ; v1(162.655,143.991) 162.655,146.496 158.843,150.308 158.843,150.917 158.218,151.542 157.609,151.542 154.719,154.432 ; v1(215.691,79.754) 215.76,79.754 216.126,79.388 v1(221.263,79.388) ; 153.621,153.334 154.719,154.432
  other v1: 156.318,48.871
5V_HVN: D15.2 FB9.1 FB10.1 J6.1 | length 198.9
  Top Layer w0.254: D15.2@51.372,162.063 51.404,162.095 v1(51.404,163.321) ; v1(115.383,162.431) 122.72,162.431 J6.1@127.985,157.166 ; FB10.1@140.639,62.375 140.639,63.266 v1(141.677,64.303) ; v1(141.029,121.417) 141.046,121.4 141.664,121.4 FB9.1@142.819,120.244 ; v1(143.695,69.119) 158.42,83.844 v1(158.42,99.72)
  Layer 2 w0.254: v1(51.404,163.321) 52.588,162.137 112.319,162.137 112.613,162.431 v1(115.383,162.431)
  Bottom Layer w0.254: J6.1@127.985,157.166 128.98,156.171 128.98,133.466 v1(141.029,121.417) 151.161,111.285 151.161,104.899 156,100.06 158.08,100.06 v1(158.42,99.72) ; v1(141.677,64.303) 143.695,66.321 v1(143.695,69.119)
5V_SW1: C36.2 C51.1 FB5.1 U7.51 U9.1 | length 99
  Top Layer w0.254: FB5.1@90.515,99.847 v1(92.249,99.847) ; C36.2@117.308,102.294 118.694,102.294 118.833,102.155 v1(118.902,102.155) ; v1(135.749,117.642) 136.452,117.642 ; U9.1@136.452,117.197 136.452,117.642 ; C51.1@136.952,118.521 136.452,118.021 136.452,117.642
  Layer 2 w0.254: v1@118.951,101.979 123.745,101.979 124.611,101.113 127.682,101.113 133.651,107.082 133.651,113.906 136.281,116.536 136.281,117.097 135.749,117.629 v1(135.749,117.642)
  Bottom Layer w0.254: v1(92.249,99.847) 92.249,104.883 88.227,108.905 88.227,116.607 89.668,118.048 97.283,118.048 102.7,112.631 117.126,112.631 118.996,110.761 118.996,102.536 118.951,102.491 118.951,102.204 v1(118.902,102.155) ; U7.51@116.508,102.294 118.737,102.294 v1@118.961,102.069
5V_SW2: C70.2 C85.1 FB14.1 U12.51 U14.1 | length 68.1
  Top Layer w0.254: FB14.1@92.066,57.973 92.289,58.196 92.634,58.196 92.838,58.4 v1(92.906,58.4) ; C70.2@113.712,52.913 C70.2@113.737,52.913 113.883,53.059 v1(114.7,53.059) ; v1(122.386,59.387) 124.801,59.387 127.366,61.952 132.714,61.952 133.397,61.269 133.551,61.269 133.551,59.785 133.619,59.718 U14.1@133.666,59.718
  Layer 2 w0.254: v1(92.906,58.4) 93.395,58.888 93.395,62.702 v2(93.963,63.27) ; v1(114.7,53.059) 115.559,53.059 116.258,52.359 119.572,52.359 120.886,53.673 120.886,57.886 v1(122.386,59.387)
  Bottom Layer w0.254: v2(93.963,63.27) 94.714,63.27 95.113,62.872 114.566,62.872 115.772,61.666 115.772,53.272 115.559,53.059 v1(114.7,53.059) 114.685,53.074 113.477,53.074 U12.51@113.462,53.089
12V_HVN: C1.1 C5.1 C6.1 C20.1 C59.1 C93.1 C115.1 C144.1 D12.1 D13.2 FB4.1 FB6.1 J6.2 K1.0 R7.1 R21.1 R25.1 R46.1 R50.1 U1.44 U4.44 U10.44 U15.44 | length 585.7
  Top Layer w0.254: C93.1@113.062,69.947 113.312,69.947 113.977,70.612 114.036,70.612 114.339,70.915 114.621,70.915 v1(114.669,70.964) ; FB6.1@149.412,45.51 149.43,45.528 150.336,45.528 v1(150.353,45.545) 150.353,45.477 150.719,45.111 150.719,44.79 150.012,44.082 R50.1@149.987,44.082
  Top Layer w0.5: K1.0@47.4,136.1 49,136.1 52.937,140.037 52.937,147.537 52.589,147.885 52.564,147.885 52.419,148.03 52.137,148.312 D12.1@49.794,148.312 49.607,148.498 R7.1@49.607,151.41 ; D13.2@48.211,162.142 47.068,162.142 46.175,161.249 46.175,156.058 47.617,154.616 53.618,154.616 54.924,153.31 54.924,146.887 ; C1.1@52.589,148.2 52.795,148.2 52.814,148.181 53.63,148.181 54.924,146.887 ; v1(55.25,146.562) 54.924,146.887 ; v1(111.9,151.75) 111.9,150.447 121.701,140.647 ; C59.1@115.693,119.369 115.993,119.669 116.608,119.669 116.998,120.058 116.998,120.069 117.369,120.441 117.981,120.441 v1(117.983,120.443) ; C115.1@117.22,133.692 117.22,133.728 C115.1@117.512,134.02 ; C115.1@117.77,134.555 117.373,134.159 117.373,135.905 121.701,140.233 121.701,140.647 ; C115.1@117.919,134.375 118.76,134.375 v1(118.762,134.374) ; v1(124.324,70.912) 124.326,70.914 124.326,70.919 124.823,71.417 128.269,71.417 134.694,64.992 142.649,64.992 146.507,61.133 v1(154.812,61.133) 160,66.321 v1(160,102.065) ; R21.1@125.37,119.237 125.403,119.271 125.403,120.867 v1(126.363,121.826) 129.463,124.926 v1(138.7,124.926) ; J6.2@127.985,155.896 127.866,155.778 127.866,155.378 124.417,151.929 124.417,146.73 C144.1@124.624,146.524 ; FB4.1@151.772,105.317 152.929,105.317 R25.1@153.029,105.417 ; R25.1@153.261,105.462 153.261,106.853 153.94,107.533 v1(154.601,107.533) ; v1(153.844,160.622) 152.837,159.616 135.291,159.616 126.244,150.569 126.244,149.094 124.624,147.474 C144.1@124.624,146.524 ; C6.1@174.661,57.459 174.661,58.564 v1(174.974,58.878) ; v1(177.355,73.762) 177.355,74.382 171.594,80.143 171.594,106.874 171.887,107.167 v1(173.367,107.167) 173.367,106.546 178.474,101.439 178.79,101.439 179.34,100.889 C5.1@179.34,99.939 ; C5.1@179.217,99.939 179.217,95.906 190.312,84.812 214.873,84.812 217.398,82.287 217.398,64.674 220.338,61.734 v1(221.263,61.734) 222.326,61.734 222.626,61.434 C20.1@222.626,61.407 ; 121.701,140.647 121.701,144.051 123.315,145.664 124.074,145.664 124.624,146.214 C144.1@124.624,146.524
  Layer 2 w0.5: v1(55.25,146.562) 58.688,150 101.325,150 103.075,151.75 v1(111.9,151.75) ; v1(114.669,70.964) 119.471,70.964 119.489,70.945 123.07,70.945 123.103,70.912 v1(124.324,70.912) ; v1(174.974,58.878) 174.974,62.308 177.355,64.689 v1(177.355,73.762)
  Bottom Layer w0.254: U15.44@113.462,70.956 113.466,70.96 114.665,70.96 v1(114.669,70.964) ; 175.012,58.291 175.012,57.605 U1.44@175.051,57.567 ; v1(221.263,61.734) 221.311,61.685 221.311,61.453 221.581,61.183 222.202,61.183 222.444,61.425 222.444,61.937 U4.44@222.542,62.035
  Bottom Layer w0.5: U10.44@116.508,120.365 117.903,120.365 v1(117.983,120.443) v1(117.983,120.443) 117.984,120.444 118.866,120.444 119.371,120.949 119.371,121.731 ; v1(118.762,134.374) 118.764,134.374 119.362,133.775 119.371,133.775 119.371,121.731 ; v1(126.363,121.826) 126.361,121.826 126.265,121.731 119.371,121.731 ; v1(138.7,124.926) 139.137,124.926 154.601,109.463 v1(154.601,107.533) 159.998,102.135 159.998,102.067 v1(160,102.065) ; v1(150.353,45.545) 150.356,45.545 151.064,46.254 151.658,46.254 153.01,47.606 153.01,59.331 v1(154.812,61.133) ; v1(153.844,160.622) 153.844,157.792 159.553,152.083 168.316,152.083 168.734,151.665 168.734,113.329 173.367,108.696 v1(173.367,107.167) ; v1(174.974,58.878) 174.976,58.876 174.976,58.328 175.012,58.291
12V_SW1: C34.1 C37.2 C38.2 C40.2 C41.1 D5.1 D6.1 R23.1 U6.28 U6.29 U7.44 | length 31.3
  Top Layer w0.254: C34.1@116.34,107.535 C34.1@115.917,107.112 116.181,106.849 v1(117.538,106.849) 118.178,106.849 119.249,107.919 120.94,107.919 123.596,110.575 D5.1@125.075,110.575 ; R23.1@132.264,103.529 R23.1@132.276,103.517
  Top Layer w0.5: D5.1@125.075,110.575 125.648,110.001 v1(126.681,110.001) ; D6.1@128.944,104.012 128.788,104.168 128.788,104.927 129.266,105.405 129.266,105.48 129.391,105.605 130.453,105.605 C38.2@130.923,105.135 ; C38.2@130.923,105.11 130.942,105.129 132.244,105.129 C40.2@132.264,105.149 ; R23.1@132.276,103.629 132.27,103.635 132.27,105.143 C40.2@132.264,105.149 ; U6.29@136.445,104.617 136.445,104.942 136.238,105.149 C37.2@133.801,105.149 C40.2@132.264,105.149
  Bottom Layer w0.254: U7.44@116.508,106.844 116.511,106.846 117.535,106.846 v1(117.538,106.849)
  Bottom Layer w0.5: v1(126.681,110.001) 128.789,107.893 v1(128.789,104.94)
12V_SW2: C68.1 C71.2 C72.2 C74.2 C75.1 D8.1 D9.1 R48.1 U11.28 U11.29 U12.44 | length 44
  Top Layer w0.254: D9.1@122.072,61.219 D9.1@122.092,61.2 ; C72.2@125.908,47.686 127.922,47.686 128.114,47.878 C71.2@129.147,47.878 129.353,47.878 C74.2@130.548,47.878 131.093,47.333 ; C72.2@125.925,47.657 125.908,47.64 125.908,46.872 v1(126.318,46.462) ; R48.1@128.859,45.214 R48.1@128.894,45.179 ; R48.1@129.056,45.502 129.353,45.799 C71.2@129.353,47.865 ; 131.093,47.32 U11.28@132.912,47.32 U11.29@132.912,46.67
  Top Layer w0.5: C68.1@113.462,58.315 113.536,58.241 v1(114.795,58.241) ; D9.1@122.092,61.2 122.092,61.047 123.084,60.055 123.662,60.055 v1(123.664,60.053) 123.664,61.303 123.841,61.481 123.841,61.531 124.671,62.361 D8.1@124.721,62.361
  Layer 2 w0.5: v1(114.795,58.241) 116.594,60.041 123.663,60.041 125.065,58.638 125.065,47.715 v1(126.318,46.462)
  Bottom Layer w0.254: U12.44@113.462,57.639 113.56,57.737 114.073,57.737 114.529,58.193 114.746,58.193 v1(114.795,58.241)
"BAT Bus+": J4.1 J4.2 K1.8 R43.1 R88.1 TP45.1
  other v1: 16.583,145.198 17.233,145.198 17.883,145.198 16.253,145.706 16.903,145.706 17.553,145.706
"BAT Bus-": J5.1 J5.2 K1.4 R2.1 R68.1 TP46.1
  other v1: 32.551,145.372 33.201,145.372 33.851,145.372 32.221,145.88 32.871,145.88 33.521,145.88
BatIN+: C60.2 C94.2 L9.1 L13.6 L18.1 L18.2 L18.3
Batt_H1_Buff: J8.7 R37.1 | length 61
  Top Layer w0.254: v1(142.536,140.158) 142.536,130.142 150.256,122.422 150.256,114.936 148.124,112.804 147.524,112.804 147.415,112.913 146.907,112.913 R37.1@146.559,113.261
  Layer 2 w0.254: v1(142.536,140.158) 142.536,145.263 153.246,155.973 153.246,157.635 152.566,158.315 149.411,158.315 J8.7@148.175,157.08
Batt_H2_Buff: J8.11 R62.1 | length 139.6
  Top Layer w0.254: R62.1@143.713,55.119 146.082,55.119 147.182,56.219 152.171,56.219 161.711,65.76 161.711,122.477 v1(152.479,131.71)
  Layer 2 w0.254: J8.11@145.635,157.166 145.635,158.022 147.23,159.617 153.402,159.617 155.061,157.958 155.061,155.6 144.018,144.557 144.018,137.659 149.967,131.71 v1(152.479,131.71)
Batt_L1_Buff: J8.9 R40.1 | length 65.2
  Top Layer w0.254: R40.1@121.011,121.42 121.011,131.622 122.056,132.667 122.056,134.951 130.898,143.793 v1(143.293,143.793)
  Layer 2 w0.254: v1(143.293,143.793) 143.293,144.564 143.202,144.655 143.202,145.358 153.65,155.806 153.65,157.803 152.733,158.719 148.545,158.719 147.338,157.513 147.338,157.166 147.13,157.166 J8.9@146.963,156.999
Batt_L2_Buff: J8.13 R65.1 | length 139.6
  Top Layer w0.254: R65.1@120.018,70.661 120.043,70.661 122.885,73.502 145.165,73.502 156.953,85.289 156.953,117.907 144.722,130.138 144.722,133.949 144.779,134.006 v1(144.779,137.886)
  Layer 2 w0.254: J8.13@144.365,157.166 144.444,157.245 144.444,157.91 146.625,160.091 154.201,160.091 155.86,158.432 155.86,155.067 144.779,143.987 v1(144.779,137.886)
Boost1_IN+: C30.2 J2.1 L6.1 TP39.1
  other v1: 31.933,48.707 32.591,48.696 33.241,48.696 33.891,48.696 34.541,48.696 35.191,48.696 35.841,48.696 36.491,48.696 37.141,48.696 37.791,48.696 38.441,48.696 39.091,48.696 39.741,48.696 40.403,48.707 41.06,48.696 41.71,48.696 42.36,48.696 43.01,48.696 43.66,48.696 44.31,48.696 44.96,48.696 45.61,48.696 46.26,48.696 46.91,48.696 47.56,48.696 48.21,48.696 48.828,48.707 49.485,48.696 50.135,48.696 50.785,48.696 51.435,48.696 52.085,48.696 31.61,49.204 32.26,49.204 32.91,49.204 33.56,49.204 34.21,49.204 34.86,49.204 35.51,49.204 36.16,49.204 36.81,49.204 37.46,49.204 38.11,49.204 38.76,49.204 39.41,49.204 40.08,49.204 40.73,49.204 41.38,49.204 42.03,49.204 42.68,49.204 43.33,49.204 43.98,49.204 44.63,49.204 45.28,49.204 45.93,49.204 46.58,49.204 47.23,49.204 47.88,49.204 48.505,49.204 49.155,49.204 49.805,49.204 50.455,49.204 51.105,49.204 51.755,49.204 52.405,49.204 31.335,55.025 31.985,55.025 32.635,55.025 33.285,55.025 33.935,55.025 34.585,55.025 35.235,55.025 35.86,55.025 36.51,55.025 37.16,55.025 37.81,55.025 38.46,55.025 39.11,55.025 39.76,55.025 40.41,55.025 41.06,55.025 41.71,55.025 42.36,55.025 43.01,55.025 43.66,55.025 44.33,55.025 44.98,55.025 45.63,55.025 46.28,55.025 46.93,55.025 47.58,55.025 48.23,55.025 48.88,55.025 49.53,55.025 50.18,55.025 50.83,55.025 51.48,55.025 52.13,55.025 34.913,55.522 43.338,55.522 51.807,55.522 31.655,55.533 32.305,55.533 32.955,55.533 33.605,55.533 34.255,55.533 35.53,55.533 36.18,55.533 36.83,55.533 37.48,55.533 38.13,55.533 38.78,55.533 39.43,55.533 40.08,55.533 40.73,55.533 41.38,55.533 42.03,55.533 42.68,55.533 44,55.533 44.65,55.533 45.3,55.533 45.95,55.533 46.6,55.533 47.25,55.533 47.9,55.533 48.55,55.533 49.2,55.533 49.85,55.533 50.5,55.533 51.15,55.533
Boost2_IN+: C224.2 J3.1 L8.1 TP43.1
Boost_S1_Buff: J8.3 R1.1 | length 117.3
  Top Layer w0.254: J8.3@150.715,157.097 150.822,157.204 150.822,157.882 151.126,158.185 155.448,158.185 161.401,152.232 167.031,152.232 167.781,151.483 167.781,112.778 170.163,110.396 170.163,78.985 177.697,71.451 177.697,65.753 174.987,63.043 173.768,63.043 173.254,62.529 173.254,62.42 173.236,62.402 173.236,61.955 R1.1@172.976,61.695
Boost_S2_Buff: J8.5 R11.1 | length 149.3
  Top Layer w0.254: J8.5@149.445,157.166 150.039,157.76 150.039,158.94 150.188,159.089 155.988,159.089 162.036,153.041 167.357,153.041 168.857,151.542 168.857,114.527 175,108.384 180.576,108.384 180.725,108.235 180.725,96.477 190.917,86.285 217.009,86.285 219.32,83.974 219.32,66.217 R11.1@219.665,65.873
CS_Bat2-sw+: R55.1 R95.1 TP24.1 | length 128.4
  Top Layer w0.254: v1(74.528,62.751) R95.1@75.618,62.751 ; v1(119.095,146.677) 121.847,149.429 R55.1@121.847,150.474
  Layer 2 w0.254: TP24.1@76.033,58.473 76.033,61.246 v1(74.528,62.751) 75.068,62.751 76.198,63.881 76.198,66.74 84.416,74.958 84.416,91.386 76.574,99.229 76.574,108.503 81.5,113.429 81.5,121.703 107.558,147.761 118.011,147.761 v1(119.095,146.677)
CS_Bat2_sw-: R73.1 R97.1 TP23.1 | length 122.4
  Top Layer w0.254: R73.1@75.667,64.27 v1(75.667,65.628) 77.381,65.628 TP23.1@79.157,67.404 ; TP23.1@78.982,67.579 ccw(c78.982,68.143) 79.381,67.744 TP23.1@79.577,67.939 ; R97.1@119.038,150.474 119.057,150.455 v1(119.057,148.396)
  Layer 2 w0.254: v1(75.667,65.628) 75.667,66.78 84,75.113 84,91.173 76.17,99.003 76.17,108.67 81,113.501 81,121.774 107.676,148.45 118.823,148.45 118.829,148.445 119.008,148.445 v1(119.057,148.396)
CS_Batt1+: J6.6 R61.1 TP20.1 | length 83.5
  Top Layer w0.254: R61.1@72.576,104.557 72.558,104.576 v1(72.558,105.768) 72.606,105.817 73.344,105.817 74.339,106.811 TP20.1@74.339,107.2
  Layer 2 w0.254: v1(72.558,105.768) 72.558,107.386 80.1,114.928 80.1,123.669 105.702,149.272 118.821,149.272 J6.6@125.445,155.896
CS_Batt1-: J6.8 R66.1 TP21.1 | length 87.3
  Top Layer w0.254: v1(71.411,102.82) 72.395,102.82 R66.1@72.539,102.964 72.564,102.964 72.912,102.616 72.912,102.103 74.333,100.682 TP21.1@74.333,100.18
  Layer 2 w0.254: v1(71.411,102.82) 71.411,106.811 79.696,115.095 79.696,123.836 105.535,149.676 118.573,149.676 124.073,155.176 124.073,155.794 J6.8@124.175,155.896
CS_Batt2+: J6.14 R55.2 | length 4.5
  Top Layer w0.254: J6.14@120.365,155.896 120.365,155.002 121.957,153.41 R55.2@121.957,152.074
CS_Batt2-: J6.16 R97.2 | length 3.8
  Top Layer w0.254: R97.2@119.038,152.074 119.095,152.131 J6.16@119.095,155.896
CS_Boost1+: C19.2 J6.7 R8.2 TP14.1 | length 212.6
  Top Layer w0.254: v1@173.476,102.327 173.476,92.102 185.578,80 211.876,80 213.602,78.274 213.602,53.447 200.235,40.08 200.235,33.866 201.566,32.535 207.915,32.535 210.04,30.41 210.04,30.385 210.388,30.037 C19.2@210.413,30.037 ; TP14.1@211.6,32.777 210.413,31.589 C19.2@210.413,30.037 ; R8.2@212.207,30.04 210.416,30.04 C19.2@210.413,30.037
  Bottom Layer w0.254: J6.7@124.175,157.166 124.175,159.422 125.245,160.492 129.384,160.492 130.85,159.026 130.85,135.883 163.57,103.164 172.943,103.164 173.092,103.015 173.092,102.803 173.476,102.419 v1(173.476,102.351)
CS_Boost1-: J6.9 R146.2 TP15.1 | length 214.6
  Top Layer w0.254: v1(173.349,103.509) 173.349,103.44 172.941,103.032 172.941,91.964 185.318,79.586 211.644,79.586 213.198,78.032 213.198,53.822 199.771,40.395 199.771,33.677 v1(201.701,31.746) ; TP15.1@203.447,22.765 204.49,23.809 v1(205.9,23.809) R146.2@207.006,23.809 R146.2@206.768,24.046
  Bottom Layer w0.254: J6.9@122.905,157.166 122.905,158.723 125.077,160.896 129.552,160.896 131.254,159.193 131.254,136.091 163.74,103.606 173.072,103.606 173.121,103.557 173.3,103.557 v1(173.349,103.509) ; v1(201.701,31.746) 201.701,30.04 205.9,25.84 v1(205.9,23.809)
